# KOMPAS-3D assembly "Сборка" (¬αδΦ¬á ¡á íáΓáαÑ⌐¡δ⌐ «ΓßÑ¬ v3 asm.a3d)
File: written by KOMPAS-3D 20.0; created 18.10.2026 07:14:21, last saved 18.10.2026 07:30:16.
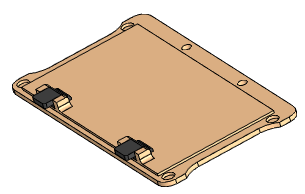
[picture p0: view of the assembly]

Document properties: Полное имя файла: D:\myProjects\Progect_esp32\box_compas\корпус\крышка на батарейный отсек v3 asm.a3d

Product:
- Part/product: Сборка
    Масса: 0.0750813
  - Component [detail]: Деталь  | qty 2  | Масса: 0.00105928; source file: крышка на батарейный отсек v3 полка.m3d
  - Component [detail]: Деталь  | Масса: 0.0729628; source file: крышка на батарейный отсек v3.m3d

Referenced files in D:\myProjects\Progect_esp32\box_compas\корпус\: крышка на батарейный отсек v3.m3d, крышка на батарейный отсек v3 полка.m3d
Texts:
  Деталь (1)
  Деталь (2)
